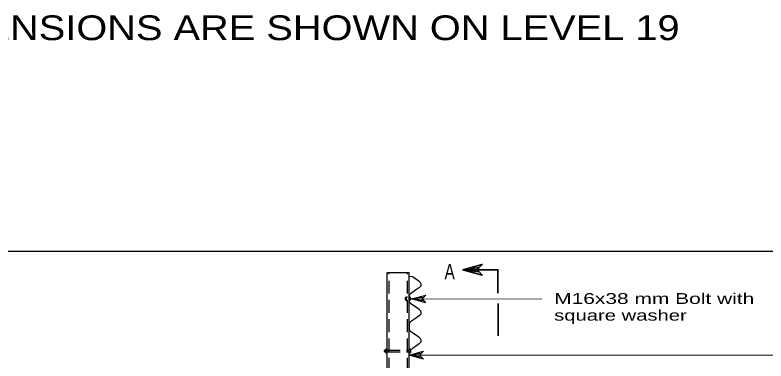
# Model space of a CAD drawing. Extents: x 13426 to 15509, y -9298 to -5111.
# Drawn here: x 15321.1 to 15412, y -5393.1 to -5351.2 of the extents above; entities that cross this region are included whole.
import ezdxf
from ezdxf.enums import TextEntityAlignment as Align

# ---------------------------------------------------------------- set-up
doc = ezdxf.new("R2010")
doc.units = 0
doc.header["$LTSCALE"] = 0.52
doc.linetypes.add('MEDIUM_DASHED', pattern=[4.5, 3, -1.5])
for name, color, linetype, lineweight in [('1', 7, 'Continuous', 13), ('15', 7, 'Continuous', 13), ('16', 7, 'Continuous', 25), ('20', 7, 'Continuous', 13), ('3', 7, 'Continuous', 25), ('30', 7, 'Continuous', 25), ('4', 7, 'Continuous', 13), ('5', 7, 'Continuous', 25)]:
    doc.layers.add(name, color=color, linetype=linetype, lineweight=lineweight)
doc.layers.add('19', color=7, linetype='Continuous')

msp = doc.modelspace()

# ---------------------------------------------------------------- linework, layer by layer
at = {"layer": '1', "lineweight": 25}
for p, q in [((15368.805, -5382.787), (15369.152, -5382.848)), ((15369.844, -5383.316), (15369.22, -5382.877)), ((15370.073, -5383.473), (15369.845, -5383.314)), ((15370.073, -5384.161), (15369.57, -5384.508)), ((15368.805, -5385.768), (15368.805, -5385.265)), ((15368.805, -5385.265), (15368.805, -5385.768)), ((15369.571, -5384.508), (15368.983, -5384.922)), ((15369.848, -5386.709), (15368.959, -5386.094)), ((15370.073, -5386.873), (15369.845, -5386.713)), ((15369.571, -5387.904), (15368.959, -5388.332)), ((15370.073, -5387.555), (15369.572, -5387.906)), ((15368.805, -5388.656), (15368.805, -5389.155)), ((15368.805, -5389.155), (15368.805, -5388.656)), ((15368.806, -5391.635), (15369.154, -5391.576)), ((15369.571, -5391.299), (15369.22, -5391.548)), ((15370.073, -5390.948), (15369.571, -5391.3))]:
    msp.add_line(p, q, dxfattribs=at)
msp.add_lwpolyline([(15370.073, -5390.265), (15369.845, -5390.106), (15368.983, -5389.503)], dxfattribs=at)
for centre, radius, start, end in [((15369.1219, -5383.0135), 0.1669, 55.00074, 79.99915), ((15369.8334, -5383.8174), 0.4173, 304.98447, 55.01608), ((15369.2213, -5385.2642), 0.4173, 124.98447, 180.00047), ((15369.2213, -5385.765), 0.4173, 179.99952, 235.01552), ((15369.8334, -5387.2117), 0.4173, 304.98447, 55.01608), ((15369.8334, -5387.2118), 0.4173, 304.98394, 55.01555), ((15369.2213, -5388.6585), 0.4173, 124.98453, 180.00053), ((15369.2213, -5389.1593), 0.4173, 179.99957, 235.01557), ((15369.8334, -5390.6061), 0.4173, 304.98394, 55.01555), ((15369.1242, -5391.4111), 0.1669, 280.00088, 304.99929)]:
    msp.add_arc(centre, radius, start, end, dxfattribs=at)
at = {"layer": '15', "linetype": 'MEDIUM_DASHED', "lineweight": 25}
for p, q in [((15368.31, -5385.378), (15368.452, -5385.378)), ((15368.31, -5385.655), (15368.452, -5385.655))]:
    msp.add_line(p, q, dxfattribs=at)
at = {"layer": '15', "lineweight": 25}
for p, q in [((15368.93, -5385.378), (15368.805, -5385.378)), ((15368.974, -5385.44), (15368.805, -5385.44)), ((15368.974, -5385.59), (15368.805, -5385.59)), ((15368.93, -5385.654), (15368.805, -5385.654))]:
    msp.add_line(p, q, dxfattribs=at)
at = {"layer": '15', "lineweight": 35}
msp.add_line((15379.579, -5390.022), (15379.579, -5386.11), dxfattribs=at)
at = {"layer": '15'}
msp.add_line((15486.643, -5392.358), (15368.805, -5392.358), dxfattribs=at)
at = {"layer": '15', "lineweight": 35}
msp.add_lwpolyline([(15375.303, -5382.012), (15379.553, -5382.012), (15379.553, -5384.866)], dxfattribs=at)
at = {"layer": '16', "lineweight": 35}
msp.add_lwpolyline([(15377.293, -5382.272), (15377.661, -5382.655), (15375.303, -5382.012), (15377.661, -5381.369), (15377.293, -5381.752), (15375.303, -5382.012), (15377.293, -5382.272), (15377.033, -5382.012), (15377.293, -5381.752)], dxfattribs=at)
at = {"layer": '16'}
for points in [[(15370.537, -5385.76), (15370.799, -5386.041), (15369.101, -5385.554), (15370.811, -5385.111), (15370.542, -5385.384), (15369.101, -5385.554), (15370.537, -5385.76), (15370.351, -5385.57), (15370.542, -5385.384)], [(15370.27, -5392.55), (15370.54, -5392.831), (15368.805, -5392.358), (15370.54, -5391.885), (15370.27, -5392.166), (15368.805, -5392.358), (15370.27, -5392.55), (15370.078, -5392.358), (15370.27, -5392.166)]]:
    msp.add_lwpolyline(points, dxfattribs=at)
at = {"layer": '3', "linetype": 'MEDIUM_DASHED'}
for p, q in [((15368.31, -5385.378), (15368.31, -5385.655)), ((15368.452, -5385.293), (15368.452, -5385.729)), ((15368.452, -5385.293), (15368.584, -5385.293)), ((15368.452, -5385.729), (15368.584, -5385.729)), ((15366.15, -5391.744), (15368.805, -5391.744)), ((15366.15, -5391.966), (15368.805, -5391.966))]:
    msp.add_line(p, q, dxfattribs=at)
at = {"layer": '3'}
for p, q in [((15368.974, -5385.61), (15368.974, -5385.422)), ((15365.875, -5391.744), (15365.959, -5391.744)), ((15365.884, -5391.776), (15365.884, -5391.936)), ((15365.931, -5391.776), (15365.931, -5391.936)), ((15365.96, -5392.029), (15365.96, -5391.68)), ((15365.96, -5391.732), (15366.15, -5391.732)), ((15366.004, -5391.636), (15366.149, -5391.636)), ((15368.996, -5391.732), (15368.805, -5391.732)), ((15368.951, -5391.636), (15368.806, -5391.636)), ((15368.996, -5392.029), (15368.996, -5391.68)), ((15365.83, -5391.922), (15365.83, -5391.789)), ((15365.875, -5391.966), (15365.959, -5391.966)), ((15365.96, -5391.981), (15366.15, -5391.981)), ((15366.004, -5392.074), (15366.149, -5392.074)), ((15368.996, -5391.981), (15368.805, -5391.981)), ((15368.951, -5392.074), (15368.806, -5392.074))]:
    msp.add_line(p, q, dxfattribs=at)
for centre, start, end in [((15368.9295, -5385.4222), 0, 90), ((15368.9295, -5385.6102), 269.99997, 0), ((15365.8747, -5391.7886), 90, 180), ((15366.0041, -5391.6801), 90, 180), ((15368.9516, -5391.6801), 0, 90), ((15365.8747, -5391.9214), 180, 269.99999), ((15366.0041, -5392.0293), 180, 269.99999), ((15368.9516, -5392.0293), 270, 0)]:
    msp.add_arc(centre, 0.0443, start, end, dxfattribs=at)
at = {"layer": '30'}
msp.add_line((15509.151, -5379.809), (15181.119, -5379.809), dxfattribs=at)
at = {"layer": '4'}
msp.add_line((15369.101, -5385.554), (15384.873, -5385.567), dxfattribs=at)
at = {"layer": '5', "linetype": 'MEDIUM_DASHED'}
for p, q in [((15366.371, -5398.941), (15366.371, -5382.344)), ((15368.584, -5398.941), (15368.584, -5382.344))]:
    msp.add_line(p, q, dxfattribs=at)
at = {"layer": '5'}
for points in [[(15366.15, -5398.941), (15366.15, -5382.344), (15368.805, -5382.344)], [(15369.137, -5398.941), (15368.805, -5398.941), (15368.805, -5382.344)]]:
    msp.add_lwpolyline(points, dxfattribs=at)

# ---------------------------------------------------------------- texts
at = {"layer": '1', "width": 1.2}
msp.add_text('METRIC DIMENSIONS ARE SHOWN ON LEVEL 19', height=3, dxfattribs=at).set_placement((15288.661, -5354.212))
at = {"layer": '19'}
for s, width, p in [('M16x38 mm Bolt with', 1.45, (15386.36, -5386.157)), ('square washer', 1.4, (15386.36, -5388.185))]:
    msp.add_text(s, height=1.307, dxfattribs=dict(at, width=width)).set_placement(p)
at = {"layer": '20', "width": 0.75}
msp.add_text('A', height=1.844, dxfattribs=at).set_placement((15373.71, -5383.162), align=Align.CENTER)

doc.saveas('drawing.dxf')
